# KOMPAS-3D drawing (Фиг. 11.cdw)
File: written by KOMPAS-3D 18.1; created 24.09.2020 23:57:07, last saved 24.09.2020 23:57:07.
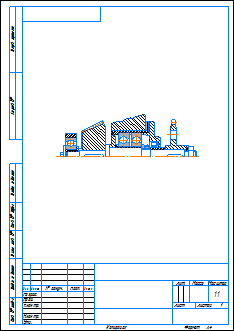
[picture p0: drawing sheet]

Sheet 1: A4, portrait

Document properties: Автор: user; Полное имя файла: C:\Users\user\Desktop\Задания\Фиг. 11.cdw

Title block, sheet 1: scale: 1:1; Количество листов документа: 1; Форматы листов документа: A4

Dimensions and other numbers on the sheet: 1:1; 1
